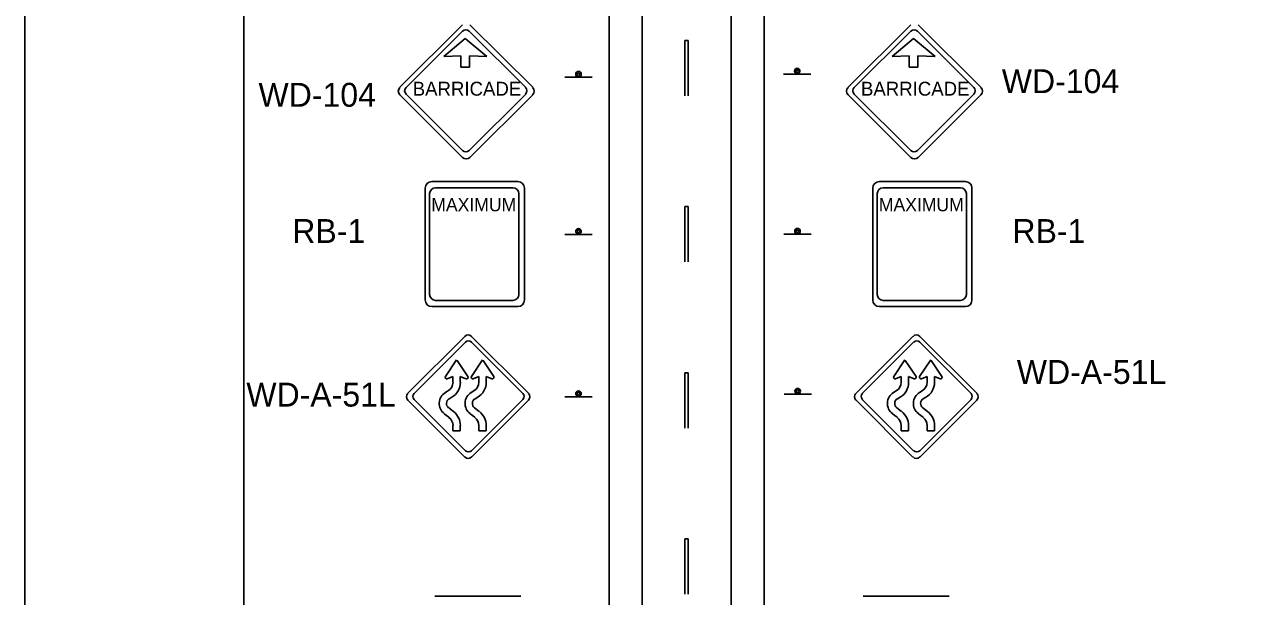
# Model space of a CAD drawing. Extents: x 2170 to 2386, y 134 to 413.
# Drawn here: x 2169.6 to 2277.6, y 223.1 to 273.1 of the extents above; entities that cross this region are included whole.
import ezdxf

# ---------------------------------------------------------------- set-up
doc = ezdxf.new("R2010")
doc.units = 0
for name, color, linetype in [('Level 10', 7, 'Continuous'), ('Level 2', 7, 'Continuous'), ('Level 20', 7, 'Continuous'), ('Level 44', 7, 'Continuous'), ('Level 60', 7, 'Continuous')]:
    doc.layers.add(name, color=color, linetype=linetype)

msp = doc.modelspace()

# ---------------------------------------------------------------- linework, layer by layer
at = {"layer": 'Level 10'}
for p, q in [((2223.52, 177.99), (2223.52, 287.5)), ((2231.26, 177.84), (2231.26, 287.27)), ((2206.34, 242.32), (2207.31, 243.78)), ((2207.35, 243.72), (2208.28, 242.32)), ((2208.6, 242.32), (2209.58, 243.78)), ((2209.62, 243.72), (2210.55, 242.32)), ((2245.46, 242.32), (2246.43, 243.78)), ((2246.47, 243.72), (2247.41, 242.32)), ((2247.72, 242.32), (2248.7, 243.78)), ((2248.74, 243.72), (2249.67, 242.32)), ((2206.99, 242.33), (2206.49, 242.13)), ((2206.99, 241.83), (2206.99, 242.33)), ((2208.13, 242.13), (2207.63, 242.33)), ((2207.63, 242.33), (2207.63, 241.83)), ((2209.26, 242.33), (2208.76, 242.13)), ((2209.26, 241.83), (2209.26, 242.33)), ((2210.4, 242.13), (2209.89, 242.33)), ((2209.89, 242.33), (2209.89, 241.83)), ((2246.11, 242.33), (2245.61, 242.13)), ((2246.11, 241.83), (2246.11, 242.33)), ((2247.25, 242.13), (2246.75, 242.33)), ((2246.75, 242.33), (2246.75, 241.83)), ((2248.38, 242.33), (2247.88, 242.13)), ((2248.38, 241.83), (2248.38, 242.33)), ((2249.52, 242.13), (2249.01, 242.33)), ((2249.01, 242.33), (2249.01, 241.83)), ((2206.33, 240.93), (2206.56, 241.07)), ((2208.59, 240.93), (2208.82, 241.07)), ((2245.45, 240.93), (2245.68, 241.07)), ((2247.71, 240.93), (2247.94, 241.07)), ((2206.89, 240.52), (2206.66, 240.38)), ((2209.15, 240.52), (2208.92, 240.38)), ((2246.01, 240.52), (2245.78, 240.38)), ((2248.27, 240.52), (2248.04, 240.38)), ((2206.64, 238.76), (2206.23, 239.08)), ((2206.62, 239.58), (2207.03, 239.26)), ((2208.91, 238.76), (2208.49, 239.08)), ((2208.88, 239.58), (2209.29, 239.26)), ((2245.76, 238.76), (2245.35, 239.08)), ((2245.74, 239.58), (2246.15, 239.26)), ((2248.03, 238.76), (2247.61, 239.08)), ((2248, 239.58), (2248.41, 239.26)), ((2206.99, 237.59), (2206.99, 238.04)), ((2207.63, 238.04), (2207.63, 237.59)), ((2209.26, 237.59), (2209.26, 238.04)), ((2209.89, 238.04), (2209.89, 237.59)), ((2246.11, 237.59), (2246.11, 238.04)), ((2246.75, 238.04), (2246.75, 237.59)), ((2248.38, 237.59), (2248.38, 238.04)), ((2249.01, 238.04), (2249.01, 237.59))]:
    msp.add_line(p, q, dxfattribs=at)
for points in [[(2207.63, 237.59), (2206.99, 237.59)], [(2209.89, 237.59), (2209.26, 237.59)], [(2246.75, 237.59), (2246.11, 237.59)], [(2249.01, 237.59), (2248.38, 237.59)]]:
    msp.add_lwpolyline(points, dxfattribs=at)
for centre, radius, start, end in [((2206.45, 242.25), 0.128, 146.2788, 291.7539), ((2208.18, 242.25), 0.128, 248.2461, 33.7212), ((2208.71, 242.25), 0.128, 146.2788, 291.7539), ((2210.44, 242.25), 0.128, 248.2461, 33.7212), ((2245.57, 242.25), 0.128, 146.2788, 291.7539), ((2247.3, 242.25), 0.128, 248.2461, 33.7212), ((2247.83, 242.25), 0.128, 146.2788, 291.7539), ((2249.56, 242.25), 0.128, 248.2461, 33.7212), ((2206.91, 239.97), 1.12, 121.1816, 232.5768), ((2206.1, 241.83), 0.897, 301.2095, 0), ((2206.1, 241.83), 1.54, 301.2095, 0), ((2209.17, 239.97), 1.12, 121.1816, 232.5768), ((2208.36, 241.83), 0.897, 301.2095, 0), ((2208.36, 241.83), 1.54, 301.2095, 0), ((2246.03, 239.97), 1.12, 121.1816, 232.5768), ((2245.22, 241.83), 0.897, 301.2095, 0), ((2245.22, 241.83), 1.54, 301.2095, 0), ((2248.29, 239.97), 1.12, 121.1816, 232.5768), ((2247.48, 241.83), 0.897, 301.2095, 0), ((2247.48, 241.83), 1.54, 301.2095, 0), ((2206.91, 239.97), 0.483, 121.1644, 232.5768), ((2209.17, 239.97), 0.483, 121.1644, 232.5768), ((2246.03, 239.97), 0.483, 121.1644, 232.5768), ((2248.29, 239.97), 0.483, 121.1644, 232.5768), ((2206.1, 238.04), 0.897, 0, 52.5572), ((2206.1, 238.04), 1.54, 0, 52.5572), ((2208.36, 238.04), 0.897, 0, 52.5572), ((2208.36, 238.04), 1.54, 0, 52.5572), ((2245.22, 238.04), 0.897, 0, 52.5572), ((2245.22, 238.04), 1.54, 0, 52.5572), ((2247.48, 238.04), 0.897, 0, 52.5572), ((2247.48, 238.04), 1.54, 0, 52.5572)]:
    msp.add_arc(centre, radius, start, end, dxfattribs=at)
at = {"layer": 'Level 2'}
for p, q in [((2227.24, 271.68), (2227.24, 266.84)), ((2227.53, 271.68), (2227.24, 271.68)), ((2227.53, 266.84), (2227.53, 271.68)), ((2227.24, 257.17), (2227.24, 252.33)), ((2227.53, 257.17), (2227.24, 257.17)), ((2227.53, 252.33), (2227.53, 257.17)), ((2227.24, 242.65), (2227.24, 237.81)), ((2227.53, 242.65), (2227.24, 242.65)), ((2227.53, 237.81), (2227.53, 242.65)), ((2227.24, 228.14), (2227.24, 223.3)), ((2227.53, 228.14), (2227.24, 228.14)), ((2227.53, 223.3), (2227.53, 228.14))]:
    msp.add_line(p, q, dxfattribs=at)
at = {"layer": 'Level 20'}
for p, q in [((2234.16, 177.84), (2234.16, 321.3)), ((2220.62, 177.82), (2220.62, 313.63))]:
    msp.add_line(p, q, dxfattribs=at)
at = {"layer": 'Level 44'}
for p, q in [((2207.83, 273.06), (2202.35, 267.59)), ((2202.9, 267.58), (2207.83, 272.5)), ((2208.41, 272.5), (2213.34, 267.58)), ((2213.95, 267.59), (2208.48, 273.06)), ((2246.95, 273.06), (2241.47, 267.59)), ((2242.02, 267.58), (2246.95, 272.5)), ((2247.53, 272.5), (2252.45, 267.58)), ((2253.07, 267.59), (2247.6, 273.06)), ((2208.07, 271.86), (2206.19, 270.27)), ((2209.95, 270.27), (2208.07, 271.86)), ((2247.19, 271.86), (2245.31, 270.27)), ((2249.07, 270.27), (2247.19, 271.86)), ((2206.19, 270.27), (2207.69, 270.35)), ((2207.69, 270.35), (2207.69, 269.35)), ((2208.45, 269.35), (2208.45, 270.35)), ((2208.45, 270.35), (2209.95, 270.27)), ((2245.31, 270.27), (2246.81, 270.35)), ((2246.81, 270.35), (2246.81, 269.35)), ((2247.57, 269.35), (2247.57, 270.35)), ((2247.57, 270.35), (2249.07, 270.27)), ((2207.69, 269.35), (2208.44, 269.35)), ((2246.81, 269.35), (2247.56, 269.35)), ((2219.15, 268.47), (2216.76, 268.47)), ((2238.24, 268.74), (2235.84, 268.74)), ((2202.35, 266.94), (2207.83, 261.46)), ((2202.36, 266.94), (2202.35, 266.94)), ((2207.83, 262.07), (2202.9, 267)), ((2213.34, 267), (2208.41, 262.07)), ((2208.48, 261.46), (2213.95, 266.94)), ((2241.47, 266.94), (2246.95, 261.46)), ((2241.47, 266.94), (2241.47, 266.94)), ((2246.95, 262.07), (2242.02, 267)), ((2252.45, 267), (2247.53, 262.07)), ((2247.6, 261.46), (2253.07, 266.94)), ((2205.15, 259.36), (2212.65, 259.36)), ((2244.21, 259.36), (2251.71, 259.36)), ((2204.57, 249.01), (2204.57, 258.78)), ((2204.96, 249.5), (2204.96, 258.3)), ((2205.48, 258.82), (2212.22, 258.82)), ((2212.75, 258.3), (2212.75, 249.5)), ((2213.23, 258.78), (2213.23, 249.01)), ((2243.63, 249.01), (2243.63, 258.78)), ((2244.02, 249.5), (2244.02, 258.3)), ((2244.54, 258.82), (2251.28, 258.82)), ((2251.8, 258.3), (2251.8, 249.5)), ((2252.28, 258.78), (2252.28, 249.01)), ((2219.15, 254.74), (2216.76, 254.74)), ((2238.26, 254.76), (2235.87, 254.76)), ((2204.96, 249.5), (2204.96, 249.5)), ((2244.02, 249.5), (2244.02, 249.5)), ((2204.57, 249.01), (2204.57, 249.01)), ((2212.65, 248.43), (2205.15, 248.43)), ((2212.22, 248.98), (2205.48, 248.98)), ((2243.63, 249.01), (2243.63, 249.01)), ((2251.71, 248.43), (2244.21, 248.43)), ((2251.28, 248.98), (2244.54, 248.98)), ((2203.05, 240.86), (2208.02, 245.83)), ((2208.08, 245.33), (2203.6, 240.85)), ((2208.61, 245.83), (2213.59, 240.86)), ((2213.09, 240.85), (2208.61, 245.33)), ((2242.17, 240.86), (2247.14, 245.83)), ((2247.2, 245.33), (2242.72, 240.85)), ((2247.73, 245.83), (2252.71, 240.86)), ((2252.21, 240.85), (2247.73, 245.33)), ((2208.02, 235.29), (2203.05, 240.27)), ((2203.6, 240.32), (2208.08, 235.84)), ((2208.61, 235.84), (2213.09, 240.32)), ((2213.59, 240.27), (2208.61, 235.29)), ((2213.59, 240.27), (2213.59, 240.27)), ((2219.15, 240.56), (2216.76, 240.56)), ((2238.29, 240.78), (2235.89, 240.78)), ((2247.14, 235.29), (2242.17, 240.27)), ((2242.72, 240.32), (2247.2, 235.84)), ((2247.73, 235.84), (2252.21, 240.32)), ((2252.71, 240.27), (2247.73, 235.29)), ((2252.7, 240.27), (2252.71, 240.27)), ((2205.41, 223.13), (2212.91, 223.13)), ((2242.79, 223.13), (2250.29, 223.13))]:
    msp.add_line(p, q, dxfattribs=at)
for centre, radius in [((2217.95, 268.74), 0.24), ((2237.04, 269.01), 0.24), ((2237.04, 269.01), 0.12), ((2217.95, 268.74), 0.12), ((2217.95, 255.01), 0.24), ((2217.95, 255.01), 0.12), ((2237.06, 255.03), 0.24), ((2237.06, 255.03), 0.12), ((2217.95, 240.83), 0.24), ((2217.95, 240.83), 0.12), ((2237.08, 241.05), 0.24), ((2237.08, 241.05), 0.12)]:
    msp.add_circle(centre, radius, dxfattribs=at)
for centre, radius, start, end in [((2208.12, 272.21), 0.412, 45, 135), ((2247.24, 272.21), 0.412, 45, 135), ((2202.68, 267.26), 0.458, 135, 225), ((2203.19, 267.29), 0.412, 135, 225), ((2213.04, 267.29), 0.412, 315, 45), ((2213.62, 267.26), 0.458, 315, 45), ((2241.8, 267.26), 0.458, 135, 225), ((2242.31, 267.29), 0.412, 135, 225), ((2252.16, 267.29), 0.412, 315, 45), ((2252.74, 267.26), 0.458, 315, 45), ((2208.12, 262.36), 0.412, 225, 315), ((2208.15, 261.79), 0.458, 225, 315), ((2247.24, 262.36), 0.412, 225, 315), ((2247.27, 261.79), 0.458, 225, 315), ((2205.15, 258.78), 0.578, 90, 180), ((2212.65, 258.78), 0.578, 360, 90), ((2244.21, 258.78), 0.578, 90, 180), ((2251.71, 258.78), 0.578, 360, 90), ((2205.48, 258.3), 0.52, 90, 180), ((2212.22, 258.3), 0.52, 360, 90), ((2244.54, 258.3), 0.52, 90, 180), ((2251.28, 258.3), 0.52, 360, 90), ((2205.48, 249.5), 0.52, 180, 270), ((2212.22, 249.5), 0.52, 270, 360), ((2244.54, 249.5), 0.52, 180, 270), ((2251.28, 249.5), 0.52, 270, 360), ((2205.15, 249.01), 0.578, 180, 270), ((2212.65, 249.01), 0.578, 270, 360), ((2244.21, 249.01), 0.578, 180, 270), ((2251.71, 249.01), 0.578, 270, 360), ((2208.32, 245.54), 0.416, 45, 135), ((2208.35, 245.06), 0.375, 45, 135), ((2247.44, 245.54), 0.416, 45, 135), ((2247.47, 245.06), 0.375, 45, 135), ((2203.34, 240.56), 0.416, 135, 225), ((2203.87, 240.59), 0.375, 135, 225), ((2212.82, 240.59), 0.375, 315, 45), ((2213.29, 240.56), 0.416, 315, 45), ((2242.46, 240.56), 0.416, 135, 225), ((2242.99, 240.59), 0.375, 135, 225), ((2251.94, 240.59), 0.375, 315, 45), ((2252.41, 240.56), 0.416, 315, 45), ((2208.35, 236.11), 0.375, 225, 315), ((2247.47, 236.11), 0.375, 225, 315), ((2208.32, 235.59), 0.416, 225, 315), ((2247.44, 235.59), 0.416, 225, 315)]:
    msp.add_arc(centre, radius, start, end, dxfattribs=at)
at = {"layer": 'Level 60'}
for points in [[(2169.62, 412.76), (2385.62, 412.76), (2385.62, 133.76), (2169.62, 133.76)], [(2188.75, 401.95), (2375.62, 401.95), (2375.62, 144.57), (2188.75, 144.57)]]:
    msp.add_lwpolyline(points, close=True, dxfattribs=at)

# ---------------------------------------------------------------- texts
at = {"layer": 'Level 10'}
for s, p in [('WD-104', (2254.89, 267.08)), ('WD-104', (2190.02, 265.89)), ('RB-1', (2192.97, 253.99)), ('RB-1', (2255.82, 253.99)), ('WD-A-51L', (2256.2, 241.68)), ('WD-A-51L', (2188.96, 239.7))]:
    msp.add_text(s, height=2.09, dxfattribs=at).set_placement(p)
at = {"layer": 'Level 44'}
for s, height, p in [('BARRICADE', 1.214, (2203.48, 266.86)), ('BARRICADE', 1.214, (2242.6, 266.86)), ('MAXIMUM', 1.147, (2205.1, 256.76)), ('MAXIMUM', 1.147, (2244.16, 256.76))]:
    msp.add_text(s, height=height, rotation=360, dxfattribs=at).set_placement(p)

doc.saveas('drawing.dxf')
